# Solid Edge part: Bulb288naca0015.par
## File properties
Author: peter
Template: iso metric part.par
Last saved by: peter
Revision: 3
Application: Solid Edge
Dichte: 11.350 kg/dm^3
Genauigkeit: 0.990
Username: peter
Material: Blei
Teilflächenformatvorlage: Grau
Füllformatvorlage: ANSI37(Blei)
Virtuelle Formatvorlage: ANSI37(Blei)
Gruppierung: Metalle/Andere Metalle
Bibliotheksname: Materials
Coef. of Thermal Exp: 2.9e-05
Thermal Conductivity: 33.0
Specific Heat: 129.0
Modulus of Elasticity: 13996356710.0
Poisson's Ratio: 0.42
Yield Stress: 0.0
Ultimate Stress: 17995315.77
Elongation: 0.0
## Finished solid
Body 1: sheet body, 1 face, 3 edges, 3 vertices.
  Faces by surface: plane 1
  Edges by curve: circle 1, line 1, spline 1
Body 2: solid body, 3 faces, 4 edges, 3 vertices.
  Faces by surface: plane 1, sphere 1, spun 1
  Edges by curve: circle 2, spline 2
Bounding box of the edges (mm; curved faces can reach further): 289.012 x 42.988 x 21.494, from (-87.2816, -21.4942, 0.4277) to (201.7306, 21.4942, 21.9219).
Spherical faces by radius (mm): R0.7696 x1
Planar faces by outward normal: -z 1
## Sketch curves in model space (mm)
line (-87.2816, 0, 0.4277) -> (200.961, 0, 0.4277)
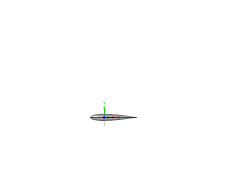
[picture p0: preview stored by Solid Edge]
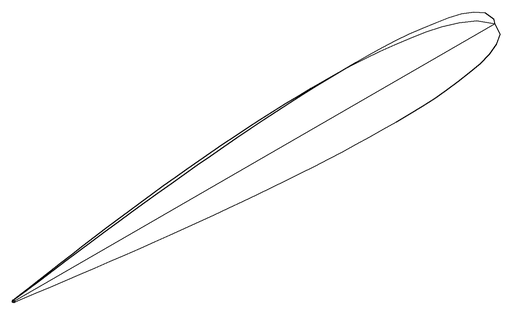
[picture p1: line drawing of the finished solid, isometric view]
